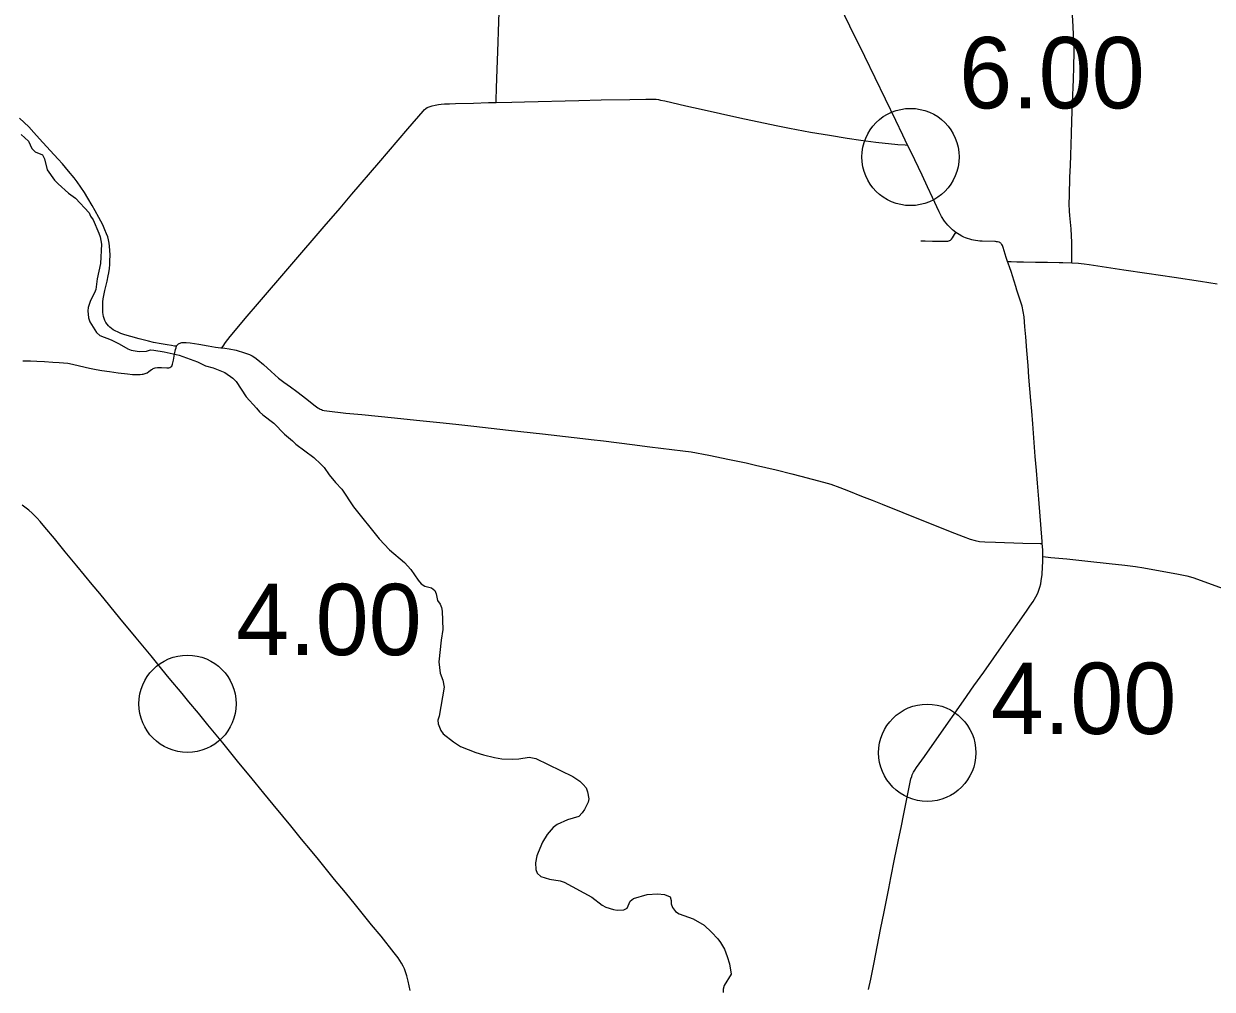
# Model space of a CAD drawing. Extents: x 1597222 to 1925846, y 496284 to 911751.
# Drawn here: x 1709106 to 1727439, y 517019 to 531911 of the extents above; entities that cross this region are included whole.
import ezdxf

# ---------------------------------------------------------------- set-up
doc = ezdxf.new("R2010")
doc.units = 0
for name, color, linetype in [('Default', 7, 'Continuous'), ('GM_X_County_Road', 7, 'Continuous'), ('GM_X_State_Route', 7, 'Continuous'), ('GM_X_Township', 7, 'Continuous'), ('GM_X_Township_Road', 7, 'Continuous')]:
    doc.layers.add(name, color=color, linetype=linetype)

msp = doc.modelspace()

# ---------------------------------------------------------------- linework, layer by layer
at = {"layer": 'Default'}
for centre in [(1722785, 529856), (1722785, 529856), (1711632, 521422), (1711632, 521422), (1723043, 520667), (1723043, 520667)]:
    msp.add_circle(centre, 750, dxfattribs=at)
at = {"layer": 'GM_X_County_Road'}
for points in [[(1725239, 529020), (1725233, 529132), (1725235, 529264), (1725243, 529542), (1725252, 529723), (1725258, 529886), (1725268, 530214), (1725276, 530411), (1725285, 530689), (1725297, 531050), (1725304, 531247), (1725309, 531476), (1725306, 531640), (1725287, 531967), (1725259, 532385)], [(1711461, 526936), (1711433, 526940), (1711383, 526948), (1711317, 526959), (1711225, 526974), (1711110, 526996), (1711030, 527014), (1710887, 527051), (1710760, 527086), (1710666, 527114), (1710605, 527135), (1710560, 527154), (1710516, 527176), (1710487, 527192), (1710461, 527210), (1710436, 527231), (1710413, 527253), (1710392, 527278), (1710374, 527305), (1710359, 527333), (1710346, 527363), (1710337, 527394), (1710331, 527426), (1710327, 527458), (1710324, 527507), (1710324, 527556), (1710327, 527621), (1710332, 527670), (1710340, 527718), (1710356, 527798), (1710391, 527941), (1710409, 528021), (1710418, 528069), (1710427, 528134), (1710433, 528200), (1710435, 528249), (1710437, 528348), (1710435, 528414), (1710429, 528479), (1710423, 528528), (1710413, 528577), (1710401, 528625), (1710385, 528672), (1710359, 528732), (1710324, 528807), (1710264, 528923), (1710209, 529025), (1710160, 529110), (1710094, 529223), (1710043, 529307), (1709989, 529390), (1709932, 529470), (1709882, 529535), (1709798, 529636), (1709702, 529749), (1709637, 529823), (1709516, 529956), (1709350, 530138), (1709262, 530235), (1709183, 530319), (1709113, 530389), (1709042, 530457)], [(1725273, 528538), (1725262, 528746), (1725244, 528955), (1725239, 529020)], [(1725276, 528225), (1725273, 528532), (1725273, 528538)], [(1724283, 528244), (1724337, 528243)], [(1724337, 528243), (1724425, 528241), (1724526, 528239)], [(1724526, 528239), (1724713, 528236)], [(1724713, 528236), (1724849, 528233), (1724897, 528232)], [(1724897, 528232), (1725078, 528229)], [(1725078, 528229), (1725136, 528227), (1725276, 528225)], [(1725276, 528225), (1725375, 528218), (1725416, 528212), (1725466, 528207), (1725542, 528195), (1726075, 528117), (1726431, 528065), (1726853, 528000), (1727258, 527938), (1727517, 527899)], [(1711434, 526814), (1711448, 526887), (1711455, 526914), (1711461, 526936)], [(1711461, 526936), (1711470, 526949), (1711477, 526959), (1711486, 526967), (1711495, 526974), (1711506, 526981), (1711517, 526985), (1711531, 526991), (1711545, 526994), (1711560, 526995), (1711581, 526995), (1711611, 526994), (1711675, 526988), (1711805, 526968), (1711949, 526941), (1712062, 526921), (1712144, 526912), (1712161, 526912)], [(1712161, 526912), (1712175, 526911), (1712209, 526908), (1712273, 526898), (1712385, 526874), (1712509, 526837), (1712588, 526809), (1712632, 526788), (1712670, 526764), (1712719, 526728), (1712804, 526654), (1712924, 526545), (1713036, 526442), (1713116, 526383), (1713219, 526309), (1713317, 526238), (1713475, 526118), (1713582, 526032), (1713644, 525988), (1713662, 525976), (1713681, 525966), (1713699, 525959), (1713717, 525952), (1713739, 525947), (1713781, 525939), (1714075, 525906), (1714319, 525884), (1714825, 525833), (1715167, 525798), (1715575, 525753), (1715819, 525730), (1716048, 525706), (1716585, 525644), (1717107, 525588), (1717595, 525530), (1717905, 525494), (1718002, 525485), (1718051, 525479), (1718490, 525422), (1718766, 525386), (1719271, 525325), (1719400, 525307), (1719674, 525256), (1719995, 525192), (1720251, 525136), (1720395, 525104), (1720714, 525028), (1720953, 524968), (1721095, 524931), (1721270, 524886), (1721444, 524840), (1721554, 524807), (1721693, 524759), (1721830, 524704), (1722027, 524624), (1722195, 524560), (1722347, 524499), (1722667, 524371), (1723398, 524078), (1723596, 524000), (1723704, 523961), (1723784, 523939), (1723849, 523927), (1723930, 523920), (1724094, 523913), (1724520, 523900), (1724783, 523895), (1724818, 523895)], [(1709091, 526714), (1709210, 526709), (1709310, 526705), (1709425, 526700), (1709553, 526693), (1709653, 526687), (1709720, 526681), (1709784, 526674), (1709856, 526658), (1709966, 526635), (1710122, 526599), (1710224, 526576), (1710312, 526563), (1710430, 526546), (1710563, 526529), (1710705, 526511), (1710784, 526503), (1710866, 526500), (1710900, 526500), (1710933, 526505), (1710949, 526507), (1710965, 526511), (1710980, 526515), (1710995, 526522), (1711010, 526529), (1711037, 526547), (1711077, 526576), (1711090, 526585), (1711105, 526593), (1711120, 526599), (1711135, 526604), (1711167, 526610), (1711200, 526611), (1711232, 526610), (1711314, 526604), (1711330, 526604), (1711346, 526606), (1711362, 526610), (1711377, 526618), (1711388, 526630), (1711395, 526644), (1711400, 526660), (1711415, 526723), (1711434, 526814)], [(1724826, 523691), (1724869, 523688), (1724950, 523680), (1725195, 523656), (1725522, 523622), (1725848, 523587), (1726093, 523560), (1726256, 523540), (1726385, 523520), (1726918, 523423), (1727046, 523395), (1727141, 523368), (1727666, 523179)]]:
    msp.add_lwpolyline(points, dxfattribs=at)
at = {"layer": 'GM_X_State_Route'}
for points in [[(1723045, 529396), (1722963, 529573), (1722794, 529928), (1722741, 530039), (1722667, 530194), (1722560, 530416), (1722080, 531405), (1721850, 531876), (1721621, 532349)], [(1723429, 528736), (1723407, 528756), (1723360, 528804), (1723309, 528867), (1723265, 528936), (1723226, 529008), (1723122, 529230), (1723045, 529396)], [(1723822, 528561), (1723790, 528566), (1723759, 528571), (1723733, 528577), (1723698, 528586), (1723666, 528596), (1723635, 528608), (1723609, 528620), (1723577, 528635), (1723534, 528659), (1723486, 528690), (1723459, 528711), (1723432, 528733), (1723429, 528736)], [(1724550, 527238), (1724537, 527392), (1724525, 527474), (1724505, 527554), (1724425, 527804), (1724408, 527858), (1724357, 528023), (1724341, 528072), (1724310, 528163), (1724283, 528244), (1724263, 528303), (1724216, 528460), (1724210, 528476), (1724203, 528491), (1724195, 528506), (1724185, 528517), (1724179, 528524), (1724170, 528532), (1724161, 528537), (1724153, 528541), (1724126, 528548), (1724111, 528549), (1724098, 528550), (1724084, 528551), (1723889, 528555), (1723854, 528558), (1723824, 528561), (1723822, 528561)], [(1724825, 523612), (1724826, 523664), (1724826, 523691), (1724825, 523795), (1724818, 523895), (1724816, 523926), (1724763, 524580), (1724744, 524826), (1724728, 525022), (1724710, 525234), (1724671, 525741), (1724654, 525937), (1724640, 526101), (1724611, 526460), (1724598, 526640), (1724579, 526869), (1724564, 527082), (1724550, 527238)], [(1715068, 517001), (1715035, 517145), (1715013, 517224), (1714994, 517286), (1714977, 517332), (1714957, 517377), (1714935, 517420), (1714909, 517462), (1714882, 517502), (1714822, 517580), (1714617, 517836), (1714471, 518014), (1714388, 518115), (1714223, 518319), (1714067, 518509), (1713902, 518713), (1713757, 518891), (1713652, 519018), (1713527, 519169), (1713392, 519334), (1713226, 519538), (1713102, 519690), (1712956, 519867), (1712810, 520044), (1712676, 520210), (1712581, 520323), (1712425, 520513), (1712175, 520817), (1711947, 521097), (1711802, 521275), (1711655, 521451), (1711550, 521578), (1711351, 521817), (1711236, 521957), (1711071, 522160), (1710840, 522438), (1710589, 522741), (1710279, 523122), (1710164, 523261), (1709924, 523552), (1709747, 523768), (1709579, 523970), (1709431, 524145), (1709358, 524234), (1709314, 524283), (1709269, 524329), (1709234, 524363), (1709184, 524406), (1709080, 524486)], [(1724628, 522926), (1724678, 523000), (1724720, 523070), (1724748, 523130), (1724761, 523161), (1724772, 523192), (1724782, 523223), (1724794, 523274), (1724803, 523320), (1724815, 523418), (1724823, 523533), (1724825, 523612)], [(1722139, 517015), (1722172, 517175), (1722223, 517433), (1722271, 517674), (1722328, 517964), (1722373, 518189), (1722408, 518366), (1722451, 518574), (1722482, 518735), (1722539, 519025), (1722593, 519298), (1722644, 519539), (1722675, 519700), (1722763, 520134), (1722792, 520262), (1722803, 520300), (1722813, 520326), (1722823, 520346), (1722833, 520367), (1722850, 520397), (1722876, 520437), (1723000, 520610), (1723225, 520933), (1723603, 521469), (1723764, 521697), (1723915, 521912), (1724227, 522354), (1724406, 522609), (1724576, 522850), (1724628, 522926)]]:
    msp.add_lwpolyline(points, dxfattribs=at)
at = {"layer": 'GM_X_Township'}
msp.add_lwpolyline([(1709068, 530201), (1709181, 530098), (1709232, 529987), (1709280, 529934), (1709395, 529890), (1709428, 529828), (1709466, 529659), (1709581, 529499), (1709636, 529441), (1709797, 529300), (1709906, 529219), (1710116, 528996), (1710137, 528945), (1710176, 528887), (1710264, 528683), (1710283, 528623), (1710304, 528513), (1710292, 528214), (1710241, 527976), (1710217, 527814), (1710198, 527762), (1710135, 527643), (1710101, 527533), (1710097, 527481), (1710105, 527377), (1710123, 527315), (1710227, 527149), (1710278, 527102), (1710452, 527034), (1710577, 526974), (1710711, 526896), (1710765, 526876), (1710889, 526856), (1711001, 526861), (1711059, 526880), (1711111, 526877), (1711271, 526851), (1711410, 526821), (1711505, 526800), (1711788, 526696), (1711910, 526637), (1712028, 526603), (1712209, 526531), (1712330, 526445), (1712382, 526392), (1712535, 526156), (1712695, 525980), (1712743, 525923), (1712794, 525878), (1712963, 525750), (1713127, 525580), (1713254, 525480), (1713302, 525427), (1713580, 525219), (1713691, 525118), (1713740, 525065), (1713815, 524952), (1713914, 524834), (1714013, 524733), (1714192, 524458), (1714590, 523964), (1714748, 523796), (1714979, 523602), (1715075, 523491), (1715188, 523327), (1715237, 523273), (1715291, 523236), (1715397, 523208), (1715448, 523168), (1715468, 523117), (1715490, 523015), (1715528, 522960), (1715551, 522906), (1715560, 522850), (1715569, 522569), (1715543, 522405), (1715509, 522067), (1715531, 521894), (1715569, 521787), (1715590, 521677), (1715512, 521229), (1715495, 521167), (1715497, 521111), (1715540, 521008), (1715575, 520958), (1715736, 520834), (1715845, 520762), (1716078, 520671), (1716196, 520635), (1716366, 520593), (1716482, 520574), (1716638, 520568), (1716741, 520574), (1716903, 520600), (1717005, 520579), (1717577, 520301), (1717684, 520228), (1717738, 520177), (1717781, 520125), (1717804, 520066), (1717821, 519958), (1717812, 519902), (1717757, 519790), (1717722, 519739), (1717671, 519681), (1717496, 519633), (1717333, 519559), (1717275, 519514), (1717181, 519403), (1717109, 519285), (1717041, 519126), (1717021, 519074), (1716999, 518968), (1717006, 518866), (1717027, 518811), (1717083, 518759), (1717217, 518717), (1717381, 518693), (1717440, 518668), (1717870, 518438), (1718029, 518314), (1718083, 518285), (1718205, 518248), (1718261, 518239), (1718363, 518242), (1718413, 518267), (1718463, 518377), (1718513, 518420), (1718723, 518482), (1718883, 518492), (1718991, 518480), (1719075, 518445), (1719092, 518387), (1719091, 518335), (1719115, 518280), (1719160, 518218), (1719216, 518183), (1719431, 518106), (1719602, 518008), (1719717, 517900), (1719812, 517797), (1719856, 517742), (1719914, 517637), (1719959, 517526), (1719994, 517412), (1720018, 517253), (1719911, 517076), (1719897, 517022), (1719896, 516968)], dxfattribs=at)
at = {"layer": 'GM_X_Township_Road'}
for points in [[(1716392, 530697), (1716393, 530726), (1716400, 530923), (1716422, 531628), (1716427, 531792), (1716438, 532087)], [(1716392, 530697), (1716636, 530702), (1716833, 530706), (1717670, 530728), (1718014, 530736), (1718457, 530745), (1718703, 530750), (1718821, 530749), (1718860, 530746), (1718898, 530741), (1718930, 530734), (1718997, 530720), (1719317, 530647), (1719557, 530592), (1720150, 530462), (1720711, 530341), (1720920, 530298), (1721243, 530241), (1721534, 530190), (1721809, 530145), (1722020, 530114), (1722248, 530086), (1722591, 530050), (1722705, 530042), (1722741, 530039)], [(1712161, 526912), (1712180, 526940), (1712217, 526995), (1712288, 527085), (1712554, 527398), (1712712, 527586), (1713738, 528782), (1713985, 529068), (1714166, 529280), (1714581, 529767), (1715030, 530290), (1715265, 530565), (1715284, 530583), (1715308, 530603), (1715329, 530617), (1715345, 530625), (1715359, 530631), (1715407, 530646), (1715454, 530655), (1715503, 530663), (1715547, 530669), (1715596, 530674), (1715673, 530678), (1715767, 530683), (1716046, 530688), (1716275, 530694), (1716392, 530697)], [(1722944, 528561), (1723012, 528560), (1723126, 528558), (1723311, 528557), (1723343, 528558), (1723363, 528559), (1723374, 528562), (1723385, 528566), (1723394, 528569), (1723401, 528573), (1723407, 528578), (1723412, 528583), (1723418, 528590), (1723431, 528608), (1723464, 528658), (1723486, 528690)]]:
    msp.add_lwpolyline(points, dxfattribs=at)

# ---------------------------------------------------------------- texts
at = {"layer": 'Default'}
for s, p in [('6.00', (1723535, 530606)), ('6.00', (1723535, 530606)), ('4.00', (1712382, 522172)), ('4.00', (1712382, 522172)), ('4.00', (1724023, 520956)), ('4.00', (1724023, 520956))]:
    msp.add_text(s, height=1100, dxfattribs=at).set_placement(p)

doc.saveas('drawing.dxf')
